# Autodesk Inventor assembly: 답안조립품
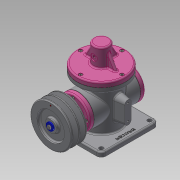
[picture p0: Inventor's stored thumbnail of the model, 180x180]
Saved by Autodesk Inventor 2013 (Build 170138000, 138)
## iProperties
Created: 2020-02
Part Number: 답안조립품
Document SubType Name: Assembly
Designer: Administrator
Author: Administrator
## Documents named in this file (21)
- C:\Users\Administrator\Desktop\600206V1019\답안조립품.iam
- C:\Users\Administrator\Desktop\600206V1019\본체.ipt
- C:\Users\Administrator\Desktop\600206V1019\E-링.ipt
- C:\Users\Administrator\Desktop\600206V1019\Ű 4 x 4 x 25.ipt
- C:\Users\Administrator\Desktop\600206V1019\V-벨트풀리.ipt
- C:\Users\Administrator\Desktop\600206V1019\가변스프링.ipt
- C:\Users\Administrator\Desktop\600206V1019\개스킷 A.ipt
- C:\Users\Administrator\Desktop\600206V1019\개스킷 B.ipt
- C:\Users\Administrator\Desktop\600206V1019\덮개.ipt
- C:\Users\Administrator\Desktop\600206V1019\뒤커버.ipt
- C:\Users\Administrator\Desktop\600206V1019\링크.ipt
- C:\Users\Administrator\Desktop\600206V1019\베어링 17 x 40 x 12.ipt
- C:\Users\Administrator\Desktop\600206V1019\볼트 M4 x 10.ipt
- C:\Users\Administrator\Desktop\600206V1019\슬라이더.ipt
- C:\Users\Administrator\Desktop\600206V1019\앞커버.ipt
- C:\Users\Administrator\Desktop\600206V1019\오일 실 17 30 8.ipt
- C:\Users\Administrator\Desktop\600206V1019\와셔 4x16.ipt
- C:\Users\Administrator\Desktop\600206V1019\육각 소켓 머리 볼트 M4 x 10.ipt
- C:\Users\Administrator\Desktop\600206V1019\클레비스 핀 6 x 22.ipt
- 클레비스 핀 6 x 22.ipt
- C:\Users\Administrator\Desktop\600206V1019\편심축.ipt
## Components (7 placed, 6 different names)
1. V-벨트풀리:1
2. Ű 4 x 4 x 25:1
3. 개스킷 A:1
4. 개스킷 A:2
5. 가변스프링:1
6. 개스킷 B:1
7. E-링:1
